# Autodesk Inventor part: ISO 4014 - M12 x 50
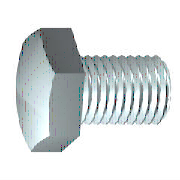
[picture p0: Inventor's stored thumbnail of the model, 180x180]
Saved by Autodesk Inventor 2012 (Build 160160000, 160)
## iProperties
Comments: To add or edit properties for Autodesk Inventor files, use iProperties.
Company: CAD-Verlag
Shininess: 64.0
Length Units: 11269
Angle Units: 11279
Time Units: 11290
Mass Units: 11283
Length Display Precision: 3
Angle Display Precision: 2
Compacted: True
Alert: To add or edit properties for Autodesk Inventor files, use iProperties.
Created: 2004-09
Part Number: ISO 4014 - M12 x 50
Vendor: Autodesk Inc.
Document SubType Name: Modeling
Designer: Greiling
Material: Standard
Description: Sechskantschraube
Standard: ISO 4014
Size Designation: M12 x 50
Density: 1 g/cm^3
Density: 0.0
Volumn: 0.0
Area: 0.0
PropertySet Name: Model Information
Control State: 0
Master: False
Checked Out: False
EGR: 1
Author: Jürgen Kronas
Revision Number: 8
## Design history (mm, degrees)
revolve "Körper" stored, may be unused: angle "d12" = 90 deg
sketch "Skizze2"
  geometry: L1 (0, 10.392)-(9, 5.196); L2 (9, 5.196)-(9, -5.196); L3 (9, -5.196)-(0, -10.392); L4 (0, -10.392)-(-9, -5.196); L5 (-9, -5.196)-(-9, 5.196); L6 (-9, 5.196)-(0, 10.392); 2 further points
  constraints: 12 end point, 1 coincident, 1 vertical, 11 other
  dimensions: "d11" = 18 distance between parallel lines of L5 L2 (= SW)
extrude "Kopf" join sketch "Skizze2" distance "d3" = 6.9 (= KOH - SD); taper "d4" = 0 deg
revolve "Fase1" stored, may be unused: angle "d21" = 90 deg
node "Volumenkörper1"
node "Volumenkörpern"
node "Oberflächenkörpern"
feature "Gewinde" dims "d15" = 30 (= GEL), "d16" = 0
chamfer "Fase2" distance "d6" = 1.07354 (= -0.5 x SPD + 0.5 x GD); stored, may be unused: second distance "d7" = 1.07364 (computed from GUL), angle "d55" = 45 deg
sketch "Skizze1"
  geometry: L1 (0, 8.315)-(0, 6); L2 (20, 6)-(50, 6); L3 (50, 6)-(50, 0); L4 (50, 0)-(-0.6, 0); L5 (-5.66, 0)-(65.18, 0) reference; L6 (-0.6, 0)-(-0.6, 8.315); L7 (-0.6, 8.315)-(0, 8.315); L8 (20, 6)-(18.926, 6); L9 (18.926, 6)-(0, 6); L10 (0, -0.832)-(0, 10.809) reference
  constraints: 16 end point, 2 collinear, 2 perpendicular, 1 parallel
  dimensions: "d0" = 50 distance between parallel lines of L3 L1 (= NLG); "d1" = 30 distance from line of L2.start L3 (= GEL); "d2" = 12 diameter of L2 L4 (= GD); "d9" = 0.6001 distance between parallel lines of L6 L1 (computed from SD); "d10" = 16.63 diameter of L7 L4 (= SD2); "d13" = 1.07364 distance of L2.start L8.end (computed from GAL); "d14" = 12 diameter of L9 L4 (= BDM)
sketch "Skizze4"
  geometry: L1 (-7.5, 9)-(-7.5, 10.392); L2 (-7.5, 10.392)-(-6.696, 10.392); L3 (-6.696, 10.392)-(-7.5, 9); L4 (-8.19, 0)-(1.47, 0) reference; L5 (-0.6, 10.392)-(-7.5, 10.392) reference; L6 (-7.5, 5.196)-(-7.5, 10.392) reference
  constraints: 6 end point, 2 collinear, 1 perpendicular, 1 vertical
  dimensions: "d5" = 30 deg angle of L3 L1 (= ANG1); "d19" = 18 diameter of L1.start L4 (= SW0)
other parameters: "NLG" = 50 [user parameter; used in 2 equation terms], "GD" = 12 (= NND) [user parameter; used in 2 equation terms], "BDM" = 12 (= NND) [user parameter; used in 1 equation term], "KOH" = 7.5 [user parameter; used in 1 equation term], "GEL" = 30 [user parameter; used in 2 equation terms], "SW" = 18 [user parameter; used in 3 equation terms], "SW0" = 18 (= SW) [user parameter; used in 1 equation term], "SPD" = 9.85293 (= NND - 1.2269 x TPU) [user parameter; used in 1 equation term], "SD2" = 16.63 [user parameter; used in 2 equation terms], "SD" = 0.6 [user parameter; used in 2 equation terms], "ANG1" = 30 deg [user parameter; used in 1 equation term], "GAL" = 1.07354 (= 0.61345 x TPU) [user parameter; used in 1 equation term], "GUL" = 1.07354 (= 0.61345 x TPU) [user parameter; used in 1 equation term], "d8" = 0, "RR" = 0.6 [user parameter], "NND" = 12 [user parameter; used in 3 equation terms], "E0" = 20.79 (= 1.155 x SW) [user parameter], "SDH" = 16.63 (= SD2) [user parameter], "THREADDIA" = 12 [user parameter; used in 1 equation term], "TPU" = 1.75 [user parameter; used in 5 equation terms], "GD1" = 9.85293 (= THREADDIA - 1.2269 x TPU) [user parameter], "PTC" = 1.75 (= TPU) [user parameter], "TOA" = 30 deg [user parameter]
